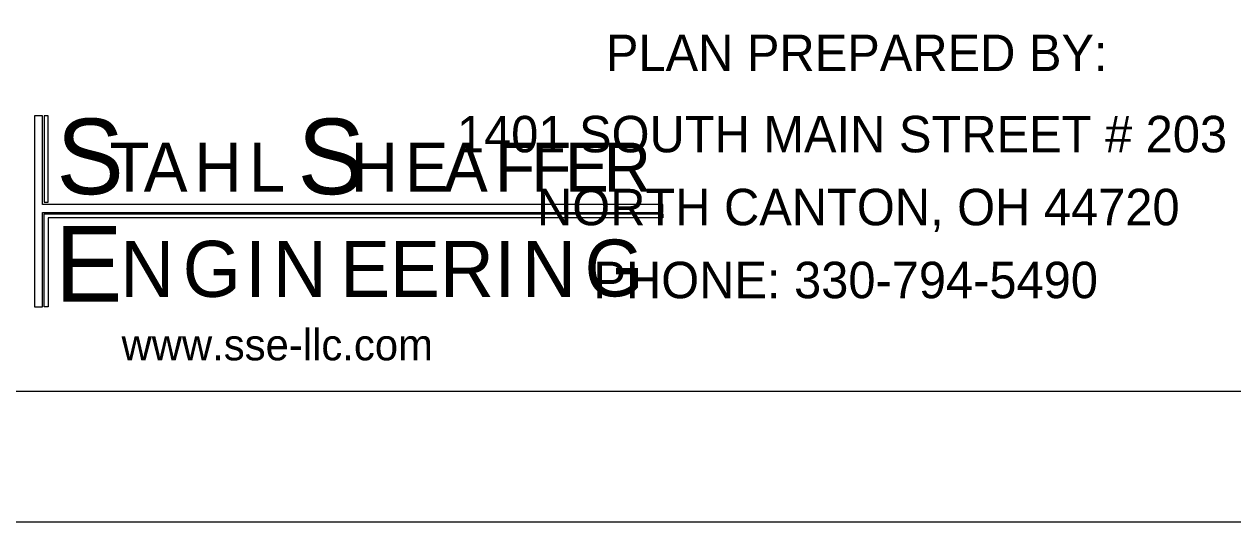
# Model space of a CAD drawing. Extents: x 421.3 to 469.3, y 221.6 to 248.2.
# Drawn here: x 423.686 to 428.323, y 221.628 to 223.539 of the extents above; entities that cross this region are included whole.
import ezdxf

# ---------------------------------------------------------------- set-up
doc = ezdxf.new("R2010")
doc.units = 0
for name, color, linetype in [('Default', 7, 'Continuous'), ('SH_Border', 7, 'Continuous'), ('SH_Cut_Line', 7, 'Continuous'), ('SH_Data', 7, 'Continuous')]:
    doc.layers.add(name, color=color, linetype=linetype)

msp = doc.modelspace()

# ---------------------------------------------------------------- linework, layer by layer
at = {"layer": 'Default'}
for points in [[(423.7254, 223.1867), (423.7254, 222.4532), (423.7558, 222.4532), (423.7558, 222.8153), (426.1359, 222.8153), (426.1359, 222.8466), (423.7558, 222.8466), (423.7558, 223.1867)], [(423.7624, 223.1867), (423.7624, 222.8555), (423.7778, 222.8555), (423.7778, 223.1867)], [(423.7624, 222.4532), (423.7624, 222.8102), (426.1359, 222.8102), (426.1359, 222.7947), (423.7778, 222.7947), (423.7778, 222.4532)]]:
    msp.add_lwpolyline(points, close=True, dxfattribs=at)
at = {"layer": 'SH_Border'}
msp.add_lwpolyline([(423.3078, 243.1284), (454.8078, 243.1284), (454.8078, 222.1284), (423.3078, 222.1284)], close=True, dxfattribs=at)
at = {"layer": 'SH_Cut_Line'}
msp.add_lwpolyline([(421.3078, 221.6284), (455.3078, 221.6284), (455.3078, 243.6284), (421.3078, 243.6284)], close=True, dxfattribs=at)

# ---------------------------------------------------------------- texts
at = {"layer": 'Default'}
for s, height, p in [('S', 0.29, (423.8095, 222.886)), ('S', 0.29, (424.7345, 222.886)), ('T', 0.188, (424.013, 222.8962)), ('A', 0.188, (424.1447, 222.8962)), ('H', 0.188, (424.3386, 222.8962)), ('L', 0.188, (424.5476, 222.8962)), ('H', 0.188, (424.9385, 222.8962)), ('E', 0.188, (425.1462, 222.8962)), ('A', 0.188, (425.2966, 222.8962)), ('F', 0.188, (425.4925, 222.8962)), ('F', 0.188, (425.6315, 222.8962)), ('E', 0.188, (425.7608, 222.8962)), ('R', 0.188, (425.909, 222.8962)), ('E', 0.29, (423.8042, 222.4739)), ('N', 0.215, (424.0539, 222.4919)), ('G', 0.215, (424.294, 222.4919)), ('I', 0.215, (424.5332, 222.4919)), ('N', 0.215, (424.6394, 222.4919)), ('E', 0.215, (424.8983, 222.4919)), ('E', 0.215, (425.0891, 222.4919)), ('R', 0.215, (425.2802, 222.4919)), ('I', 0.215, (425.4894, 222.4919)), ('N', 0.215, (425.5952, 222.4919)), ('G', 0.218, (425.8359, 222.4937)), ('www.sse-llc.com', 0.12, (424.0593, 222.2483))]:
    msp.add_text(s, height=height, dxfattribs=at).set_placement(p)
at = {"layer": 'SH_Data'}
for s, p in [('PLAN PREPARED BY:', (425.9176, 223.3587)), ('                      1401 SOUTH MAIN STREET # 203 ', (424.2017, 223.0467)), ('                            NORTH CANTON, OH 44720 ', (424.1968, 222.7667)), ('                               PHONE: 330-794-5490 ', (424.2573, 222.4867))]:
    msp.add_text(s, height=0.14, dxfattribs=at).set_placement(p)

doc.saveas('drawing.dxf')
